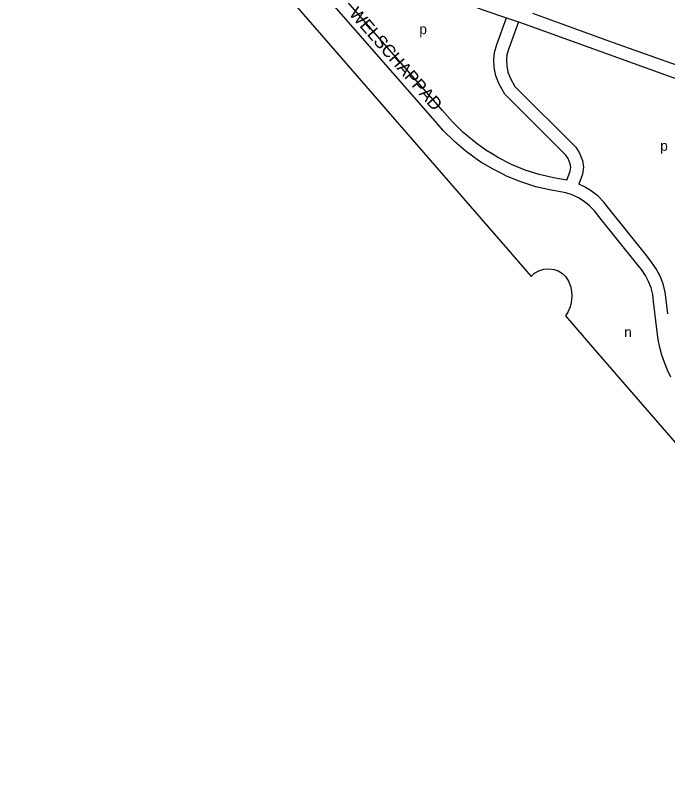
# Model space of a CAD drawing. Extents: x 156066 to 157805, y 383432 to 385631.
# Drawn here: x 156119.8 to 156377.3, y 384867 to 385173.1 of the extents above; entities that cross this region are included whole.
import ezdxf

# ---------------------------------------------------------------- set-up
doc = ezdxf.new("R2010")
doc.units = 0
for name, color, linetype in [('BLT_Basislijn', 7, 'Continuous'), ('BLT_Centroide', 7, 'Continuous'), ('BLT_Straatnaam', 7, 'Continuous'), ('BLT_Vlakafsluiter', 7, 'Continuous')]:
    doc.layers.add(name, color=color, linetype=linetype)

msp = doc.modelspace()

# ---------------------------------------------------------------- linework, layer by layer
at = {"layer": 'BLT_Basislijn'}
for p, q in [((156318.49, 385170.58), (156320.75, 385169.82)), ((156320.75, 385169.82), (156444.74, 385125.05)), ((156240.74, 385165.29), (156314.28, 385080.63)), ((156314.28, 385080.63), (156323.5, 385070.01)), ((156337, 385054.45), (156340.3, 385050.65))]:
    msp.add_line(p, q, dxfattribs=at)
for points in [[(156119.85, 385304.15), (156167.15, 385250), (156240.74, 385165.29)], [(156302.14, 385122.41), (156300.96, 385123.27), (156296.56, 385127.03), (156292.46, 385131.15), (156288.52, 385135.6), (156225.39, 385207.9), (156221.34, 385212.4), (156213.09, 385221.18), (156205.45, 385228.87), (156205.05, 385229.39), (156204.63, 385230.11), (156204.27, 385231.11), (156203.75, 385233.66), (156202.6, 385239.62)], [(156303.9, 385115.09), (156302.89, 385115.7), (156297.87, 385119.33), (156293.16, 385123.36), (156288.81, 385127.73), (156284.77, 385132.31), (156221.65, 385204.59)], [(156260.46, 385195.61), (156264.31, 385193.4), (156268.2, 385191.26), (156272.13, 385189.19), (156276.09, 385187.19), (156280.09, 385185.26), (156284.12, 385183.41), (156288.19, 385181.62), (156292.29, 385179.92), (156296.41, 385178.28), (156300.57, 385176.72), (156304.75, 385175.24), (156313.75, 385172.19)], [(156324.02, 385174.01), (156355.85, 385162.45), (156400.12, 385146.74)], [(156337.63, 385108.04), (156338.91, 385111.64), (156339.12, 385113.17), (156338.95, 385114.45), (156338.05, 385116.61), (156337.18, 385117.97), (156313.09, 385142.03), (156310.8, 385145.99), (156309.53, 385149.29), (156308.87, 385152.57), (156308.73, 385155.72), (156309, 385158.43), (156309.88, 385161.64), (156313.75, 385172.19)], [(156318.49, 385170.58), (156314.65, 385160.12), (156313.94, 385157.52), (156313.74, 385155.58), (156313.84, 385153.18), (156314.35, 385150.69), (156315.33, 385148.15), (156317.09, 385145.11), (156341.09, 385121.13), (156342.5, 385118.94), (156343.81, 385115.76), (156344.17, 385113.17), (156343.79, 385110.45), (156342.38, 385106.48)], [(156308.08, 385118.4), (156305.66, 385119.87), (156302.14, 385122.41)], [(156337.63, 385108.04), (156335.3, 385108.5), (156332.34, 385109), (156329.55, 385109.58), (156326.72, 385110.3), (156321.17, 385112.05), (156315.79, 385114.24), (156310.61, 385116.85), (156308.08, 385118.4)], [(156311.33, 385110.89), (156308.18, 385112.48), (156303.9, 385115.09)], [(156378.67, 385030.2), (156377.31, 385033.06), (156376.12, 385035.98), (156375.12, 385038.98), (156374.29, 385042), (156373.64, 385045.11), (156373.2, 385048.17), (156371.88, 385060.12), (156371.5, 385062.92), (156370.84, 385065.55), (156369.87, 385068.06), (156368.61, 385070.45), (156367.04, 385072.71), (156365.21, 385075), (156350.28, 385093.76), (156348.46, 385096), (156346.56, 385097.95), (156344.45, 385099.63), (156342.15, 385101.06), (156339.72, 385102.2), (156337.15, 385103.03), (156334.4, 385103.58), (156331.41, 385104.09), (156328.42, 385104.71), (156325.35, 385105.48), (156319.47, 385107.34), (156313.72, 385109.69), (156311.33, 385110.89)], [(156377.45, 385055.22), (156376.85, 385060.73), (156376.41, 385063.87), (156375.61, 385067.06), (156374.43, 385070.13), (156372.89, 385073.05), (156371.05, 385075.7), (156369.12, 385078.11), (156354.18, 385096.89), (156352.2, 385099.33), (156349.92, 385101.67), (156347.34, 385103.72), (156344.54, 385105.47), (156342.38, 385106.48)], [(156323.5, 385070.01), (156324.88, 385071.28), (156326.58, 385072.28), (156328.47, 385072.9), (156330.39, 385073.09), (156332.53, 385072.82), (156334.22, 385072.22), (156335.91, 385071.19), (156337.24, 385069.93), (156338.28, 385068.14), (156339.03, 385066.19), (156339.49, 385064.03), (156339.59, 385062.15), (156339.32, 385059.67), (156338.85, 385057.97), (156338.06, 385056.15), (156337, 385054.45)], [(156340.3, 385050.65), (156349.3, 385040.29), (156443.48, 384931.76), (156500, 384866.97)]]:
    msp.add_lwpolyline(points, dxfattribs=at)
at = {"layer": 'BLT_Vlakafsluiter'}
msp.add_line((156313.75, 385172.19), (156318.49, 385170.58), dxfattribs=at)

# ---------------------------------------------------------------- texts
at = {"layer": 'BLT_Centroide'}
for s, p in [('p', (156279.35, 385165.71)), ('p', (156374.48, 385119.66)), ('n', (156360.25, 385046.05))]:
    msp.add_text(s, height=4, dxfattribs=at).set_placement(p)
at = {"layer": 'BLT_Straatnaam'}
msp.add_text('WELSCHAPPAD', height=5, rotation=311.1929, dxfattribs=at).set_placement((156251.34, 385173.63))

doc.saveas('drawing.dxf')
